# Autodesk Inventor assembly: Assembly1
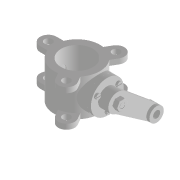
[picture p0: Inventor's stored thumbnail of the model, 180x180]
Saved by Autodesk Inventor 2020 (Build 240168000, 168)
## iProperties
Created: 2019-03
Part Number: Assembly1
Document SubType Name: Assembly
Designer: LENOVO-CADCIM
Author: LENOVO-CADCIM
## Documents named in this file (10)
- D:\Autodesk Inventor_2020\Resources1\c09\Butterfly Valve\Assembly1.iam
- D:\Autodesk Inventor_2020\Resources1\c09\Butterfly Valve\Body.ipt
- D:\Autodesk Inventor_2020\Resources1\c09\Butterfly Valve\Shaft.ipt
- D:\Autodesk Inventor_2020\Resources1\c09\Butterfly Valve\Retainer.ipt
- D:\Autodesk Inventor_2020\Resources1\c09\Butterfly Valve\Arm1.ipt
- D:\Autodesk Inventor_2020\Resources1\c09\Butterfly Valve\Plate.ipt
- D:\Autodesk Inventor_2020\Resources1\c09\Butterfly Valve\scew1.ipt
- D:\Autodesk Inventor_2020\Resources1\c09\Butterfly Valve\Screw.ipt
- D:\Autodesk Inventor_2020\Resources1\c09\Butterfly Valve\Parallel key.ipt
- D:\Autodesk Inventor_2020\Resources1\c09\Butterfly Valve\Nut.ipt
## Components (12 placed, 9 different names)
1. Body:1 — Insert:1, Insert:2, Mate:1, Angle:4
2. Shaft:1 — Insert:1, Insert:3, Insert:4, Mate:3, Insert:11
3. Retainer:1 — Insert:2, Mate:1, Insert:7, Insert:8, Insert:9, Insert:10
4. Arm1:1 — Insert:10, Mate:2, Flush:1
5. Plate:1 — Insert:3, Insert:4, Insert:5, Insert:6
6. scew1:1 — Insert:5
7. scew1:2 — Insert:6
8. Screw:1 — Insert:7
9. Screw:2 — Insert:8
10. Screw:3 — Insert:9
11. Parallel key:1 — Mate:2, Mate:3, Flush:1
12. Nut:1 — Insert:11, Angle:4
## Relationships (16: Insert 11, Mate 3, Flush 1, Angle 1)
- Insert:1: Body:1 ↔ Shaft:1
- Insert:2: Body:1 ↔ Retainer:1
- Mate:1: Body:1 ↔ Retainer:1
- Insert:3: Shaft:1 ↔ Plate:1
- Insert:4: Shaft:1 ↔ Plate:1
- Insert:5: Plate:1 ↔ scew1:1
- Insert:6: Plate:1 ↔ scew1:2
- Insert:7: Retainer:1 ↔ Screw:1
- Insert:8: Retainer:1 ↔ Screw:2
- Insert:9: Retainer:1 ↔ Screw:3
- Insert:10: Retainer:1 ↔ Arm1:1
- Mate:2: Arm1:1 ↔ Parallel key:1
- Mate:3: Shaft:1 ↔ Parallel key:1
- Flush:1: Arm1:1 ↔ Parallel key:1
- Insert:11: Shaft:1 ↔ Nut:1
- Angle:4: Body:1 ↔ Nut:1
